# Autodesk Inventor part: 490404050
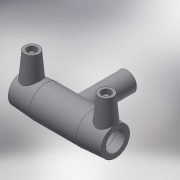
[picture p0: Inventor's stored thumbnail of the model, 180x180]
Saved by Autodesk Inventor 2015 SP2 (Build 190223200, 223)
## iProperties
Created: 2017-06
Part Number: 490404050
Material: Generic
Description: PLASSON TEE 50-50-50
Document SubType Name: Modeling
Designer: KIM
Mass: 57.3761 g
Surface Area: 241.06 cm^2
Volume: 57.3761 cm^3
Density: 1 g/cm^3
Appearance: Default
Author: KIM
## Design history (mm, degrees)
derived "490404.ipt"
feature "Solid1::490404.ipt"
tag "TaggingFeature1"
body "Solid1"
other parameters: "d0" = 139, "d2" = 68, "d3" = 48, "d4" = 34.75, "d5" = 61.2, "d6" = 47.5, "d8" = 168 deg, "d10" = 19.2, "d11" = 6.4, "d13" = 139, "d14" = 17.6296, "d17" = 45, "d19" = 3.52592, "d20" = 168 deg, "d22" = 63.24, "d23" = 68, "d24" = 61.3428, "d25" = 135 deg, "d26" = 97.3, "d27" = 135 deg, "d29" = 52, "d30" = 15, "d31" = 55.6, "d34" = 5 deg, "d35" = 15, "d39" = 5 deg, "d40" = 9.6, "d41" = 4.8, "d42" = 6, "d43" = 0, "d45" = 4, "d46" = 14, "d47" = 0, "d48" = -102, "d51" = 0, "d54" = 0, "d55" = 61.2, "d56" = 68, "d57" = 48.65, "d58" = 135 deg, "d59" = 48, "d60" = 48, "d61" = 135 deg, "d62" = 102, "d72" = 63.245, "d73" = 31.6225, "d74" = -102, "d75" = 52.5, "d77" = 0, "d80" = 0, "d82" = 68, "d83" = 0, "d84" = 3, "d85" = 0, "d86" = 3, "d87" = 0, "d88" = 13.92, "d89" = 3.48, "d90" = 13.92, "L_" = 139, "L_1" = 48, "D_" = 68, "A_" = 52, "d_2" = 12, "H_" = 102
